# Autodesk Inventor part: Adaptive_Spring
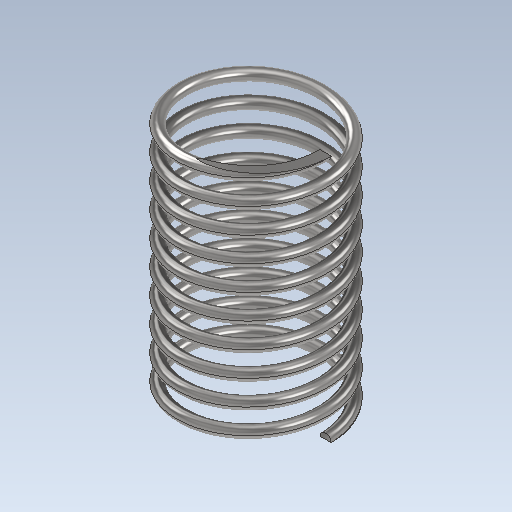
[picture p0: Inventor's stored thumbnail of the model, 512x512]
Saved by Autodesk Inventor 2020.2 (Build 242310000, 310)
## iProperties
Created: 2020-01
Part Number: Adaptive_Spring
Material: Iron, Malleable
Document SubType Name: Modeling
Designer: thira
Density: 7.15 g/cm^3
Appearance: Semi-Polished
Author: thira
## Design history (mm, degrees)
sketch "Sketch1"
  geometry: C1 r 100 at (0, 0); 1 further point
  constraints: 1 centre point, 1 coincident
  dimensions: "d0" = 200 diameter of C1
extrude "Extrusion1" new body sketch "Sketch1" taper "d2" = 0 deg; distance "Height" = 330
sketch "Sketch2"
  geometry: L1 (100, 330)-(100, 0) reference; L2 (100, 0)-(-100, 0) reference; L3 (-100, 0)-(-100, 330) reference; L4 (-100, 330)-(100, 330) reference; C1 r 7.5 at (92.5, 0); 1 further point
  constraints: 1 centre point, 1 point on line, 1 tangent
  dimensions: "d3" = 15 diameter of C1
coil "Coil1" sketch "Sketch2" pitch "d4" = 33 (= 0.1 x Height); turns "d6" = 1; dims "d5" = 330 (= Height), "d7" = 0, angle "d8" = 90 deg, angle "d9" = 90 deg, "d10" = 0, "d11" = 0
body "Solid1"
node "Project Cut Edges1"
